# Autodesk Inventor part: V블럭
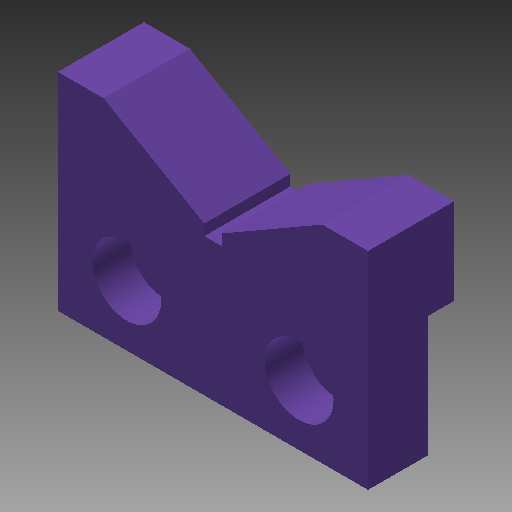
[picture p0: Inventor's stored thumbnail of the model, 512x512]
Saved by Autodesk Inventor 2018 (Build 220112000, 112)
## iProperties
Created: 2020-03
Part Number: V블럭
Material: 알루미늄 6061
Document SubType Name: Modeling
Designer: mduedu
Density: 2.71 g/cm^3
Appearance: 보라색
Mass: 15.3261 g
Surface Area: 29.4682 cm^2
Volume: 5.65539 cm^3
Author: mduedu
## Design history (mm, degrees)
sketch "스케치1"
  geometry: L1 (-18, 0)-(18, 0); L2 (18, 0)-(18, 24); L3 (-18, 24)-(-18, 0); L4 (-12.679, 24)-(-1, 17.257); L5 (1, 17.257)-(12.679, 24); L6 (1, 17.257)-(1, 16); L7 (1, 16)-(-1, 16); L8 (-1, 16)-(-1, 17.257); L9 (18, 24)-(12.679, 24); L10 (-12.679, 24)-(-18, 24); L11 (0, 0)-(0, 16); C1 r 15 at (0, 34); 1 further point
  constraints: 22 end point, 4 parallel, 3 vertical, 2 horizontal, 2 midpoint, 1 centre point, 1 coincident, 1 collinear, 1 equal length, 1 horizontal alignment, 1 perpendicular, 1 tangent, 1 vertical alignment
  dimensions: "d0" = 36 distance of L1.start L1.end; "d2" = 24 distance of L1.end L2.end; "d3" = 2 distance of L6.end L7.end; "d5" = 8 distance from line of L7 L2.end; "d6" = 120 deg angle of L5 L4; "d7" = 30 diameter of C1; "d8" = 34 distance from line of C1.centre L1
extrude "돌출1" new body sketch "스케치1" distance "d9" = 10; taper "d10" = 0 deg
sketch "스케치2"
  geometry: L1 (0, 0)-(-3, 0); L2 (-3, 0)-(-3, 14); L3 (-3, 14)-(0, 14); L4 (0, 14)-(0, 0)
  constraints: 8 end point, 2 parallel, 1 horizontal, 1 perpendicular
  dimensions: "d11" = 3 distance of L2.end L3.end; "d12" = 14 distance of L1.end L2.end
extrude "돌출2" cut sketch "스케치2" extent not by distance; stored distance "d13" = 10; taper "d14" = 0 deg
sketch "스케치3"
  geometry: L1 (-18, 0)-(18, 0) reference; 3 further points
  constraints: 1 horizontal alignment
  dimensions: "d15" = 10 horizontal distance of point (-10, 7) point (0, 0); "d16" = 20 distance of point (10, 7) point (-10, 7); "d17" = 7 distance from line of point (10, 7) L1
hole "구멍1" sketch "스케치3" at (-10, 7), (10, 7) diameter "d18" = 4.5; stored, may be unused: countersink angle "d22" = 90 deg, drill point angle "d24" = 118 deg; dims "d19" = 6, "d20" = 8, "d21" = 4.4, "d23" = 8
node "솔리드1"
